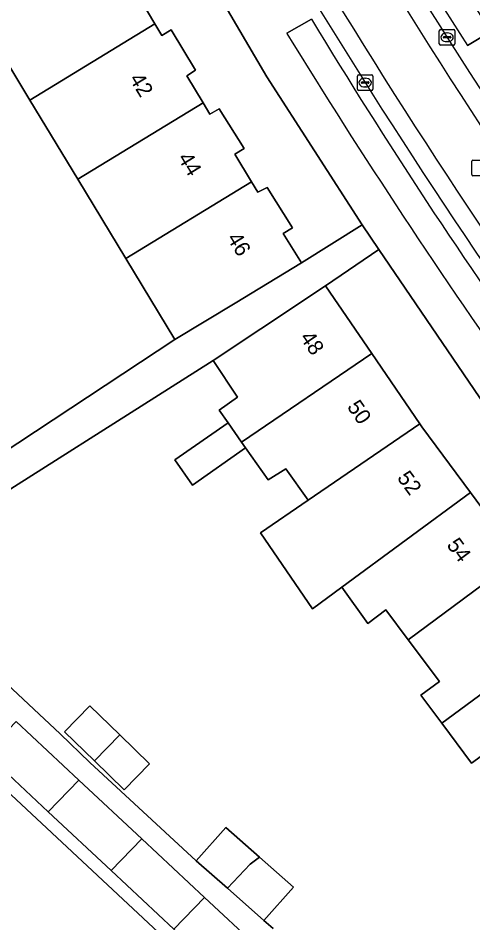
# Model space of a CAD drawing. Extents: x 162073 to 163043, y 381818 to 382561.
# Drawn here: x 162508.8 to 162538.1, y 382247.3 to 382305.6 of the extents above; entities that cross this region are included whole.
import ezdxf

# ---------------------------------------------------------------- set-up
doc = ezdxf.new("R2010")
doc.units = 0
for name, color, linetype in [('IMGEO_Erf', 7, 'Continuous'), ('IMGEO_Fietspad_gesloten', 7, 'Continuous'), ('IMGEO_Kolk', 7, 'Continuous'), ('IMGEO_Pand', 7, 'Continuous'), ('IMGEO_Pand_nummerreeks', 7, 'Continuous'), ('IMGEO_Parkeervlak_open', 7, 'Continuous'), ('IMGEO_Rijbaan_lokaal_open', 7, 'Continuous'), ('IMGEO_Rioolput', 7, 'Continuous'), ('IMGEO_Voetpad_open', 7, 'Continuous')]:
    doc.layers.add(name, color=color, linetype=linetype)

msp = doc.modelspace()

# ---------------------------------------------------------------- linework, layer by layer
at = {"layer": 'IMGEO_Erf'}
for points in [[(162516.63, 382306.92), (162517.645, 382305.206), (162518.089, 382304.457), (162518.686, 382304.825), (162520.246, 382302.222), (162519.701, 382301.866), (162520.745, 382300.11), (162521.172, 382299.391), (162521.781, 382299.733), (162523.38, 382297.169), (162522.784, 382296.8), (162523.864, 382295.026), (162524.268, 382294.363), (162524.877, 382294.667), (162526.501, 382292.052), (162525.892, 382291.696), (162527.085, 382289.792), (162530.981, 382292.245), (162524.856, 382301.801), (162515.515, 382317.726)], [(162518.927, 382284.853), (162515.757, 382290.085), (162512.666, 382295.187), (162509.575, 382300.289), (162506.484, 382305.391)], [(162567.838, 382244.089), (162562.574, 382250), (162557.981, 382255.464), (162545.965, 382270.851), (162540.59, 382278.138), (162532.058, 382290.664), (162528.627, 382288.327), (162531.6, 382283.968), (162534.706, 382279.414), (162534.828, 382279.235), (162537.954, 382275.004), (162541.079, 382270.777), (162544.42, 382266.255), (162547.873, 382261.582), (162547.996, 382261.416), (162551.264, 382257.471), (162554.603, 382253.441), (162557.453, 382250), (162558.225, 382249.068), (162561.821, 382244.727)], [(162457.619, 382263.189), (162459.18, 382261.904), (162475.761, 382248.251), (162478.317, 382251.355), (162474.824, 382254.232), (162476.565, 382256.346), (162480.058, 382253.468), (162483.451, 382257.921), (162481.553, 382259.466), (162483.988, 382262.459), (162486.44, 382265.471), (162488.329, 382263.933), (162488.605, 382263.708), (162491.308, 382267.028), (162489.142, 382268.791), (162491.617, 382271.833), (162493.971, 382274.724), (162496.137, 382272.961), (162498.99, 382276.207), (162500.055, 382275.334), (162502.069, 382273.725), (162502.096, 382273.753), (162518.927, 382284.853)], [(162539.275, 382258.445), (162538.019, 382257.551), (162536.115, 382260.119), (162534.774, 382261.928), (162535.96, 382262.823), (162533.946, 382265.507), (162532.504, 382267.429), (162531.359, 382266.556), (162529.688, 382268.898), (162527.79, 382267.496), (162524.439, 382272.404), (162527.503, 382274.496), (162526.074, 382276.525), (162524.928, 382275.811), (162523.483, 382277.871), (162520.066, 382275.477), (162518.933, 382277.094), (162522.35, 382279.488), (162521.783, 382280.298), (162522.969, 382281.133), (162521.381, 382283.497), (162504.175, 382272.599)], [(162546.943, 382219.45), (162494.331, 382268.629), (162482.206, 382253.929), (162481.569, 382253.156), (162483.282, 382251.74), (162483.952, 382251.186), (162485.979, 382249.511), (162488.441, 382247.475), (162490.227, 382246)], [(162507.097, 382263.591), (162511.538, 382259.449), (162513.452, 382257.589), (162520.303, 382251.26), (162522.204, 382253.41), (162524.377, 382251.488), (162526.565, 382249.554), (162524.664, 382247.404), (162525.253, 382246.883)]]:
    msp.add_lwpolyline(points, dxfattribs=at)
msp.add_lwpolyline([(162515.66, 382255.833), (162513.742, 382257.701), (162511.824, 382259.57), (162513.453, 382261.242), (162515.371, 382259.374), (162517.289, 382257.505)], close=True, dxfattribs=at)
at = {"layer": 'IMGEO_Fietspad_gesloten'}
for centre, radius, start, end in [((162921.44, 382547.896), 456.819, 210.01231, 214.91275), ((162945.03, 382562.574), 483.34, 210.21879, 214.72337), ((162877.852, 382519.575), 408.409, 209.6326, 215.19334), ((162906.267, 382538.255), 443.6, 210.014, 215.04595)]:
    msp.add_arc(centre, radius, start, end, dxfattribs=at)
at = {"layer": 'IMGEO_Kolk'}
for p, q in [((162535.955, 382303.914), (162535.955, 382304.766)), ((162536.03, 382304.84), (162536.882, 382304.84)), ((162536.443, 382304.62), (162536.468, 382304.62)), ((162536.956, 382304.766), (162536.956, 382303.914)), ((162536.214, 382304.334), (162536.214, 382304.346)), ((162536.652, 382304.297), (162536.254, 382304.297)), ((162536.257, 382304.383), (162536.655, 382304.383)), ((162536.466, 382304.06), (162536.441, 382304.06)), ((162536.698, 382304.346), (162536.698, 382304.334)), ((162536.882, 382303.84), (162536.03, 382303.84)), ((162530.68, 382300.992), (162530.68, 382301.844)), ((162530.755, 382301.918), (162531.607, 382301.918)), ((162531.168, 382301.698), (162531.193, 382301.698)), ((162531.681, 382301.844), (162531.681, 382300.992)), ((162530.939, 382301.412), (162530.939, 382301.424)), ((162531.377, 382301.375), (162530.979, 382301.375)), ((162530.982, 382301.461), (162531.38, 382301.461)), ((162531.191, 382301.138), (162531.166, 382301.138)), ((162531.423, 382301.424), (162531.423, 382301.412)), ((162531.607, 382300.918), (162530.755, 382300.918))]:
    msp.add_line(p, q, dxfattribs=at)
for points in [[(162535.955, 382303.914), (162535.955, 382304.766)], [(162536.03, 382304.84), (162536.882, 382304.84)], [(162536.956, 382304.766), (162536.956, 382303.914)], [(162536.882, 382303.84), (162536.03, 382303.84)], [(162530.68, 382300.992), (162530.68, 382301.844)], [(162530.755, 382301.918), (162531.607, 382301.918)], [(162531.681, 382301.844), (162531.681, 382300.992)], [(162531.607, 382300.918), (162530.755, 382300.918)]]:
    msp.add_lwpolyline(points, dxfattribs=at)
for centre, radius, start, end in [((162536.032, 382304.764), 0.0765, 91.55205, 178.44795), ((162536.032, 382304.764), 0.0765, 91.55205, 178.44795), ((162536.88, 382304.764), 0.0765, 1.55205, 88.44795), ((162536.88, 382304.764), 0.0765, 1.55205, 88.44795), ((162536.254, 382304.343), 0.0403, 85.87752, 175.75265), ((162536.251, 382304.333), 0.0366, 178.93798, 274.71019), ((162536.655, 382304.34), 0.043, 264.86636, 352.45326), ((162536.659, 382304.345), 0.0386, 1.73085, 96.63898), ((162536.032, 382303.916), 0.0765, 181.55205, 268.44795), ((162536.032, 382303.916), 0.0765, 181.55205, 268.44795), ((162536.88, 382303.916), 0.0765, 271.55205, 358.44795), ((162536.88, 382303.916), 0.0765, 271.55205, 358.44795), ((162530.757, 382301.842), 0.0765, 91.55205, 178.44795), ((162530.757, 382301.842), 0.0765, 91.55205, 178.44795), ((162531.605, 382301.842), 0.0765, 1.55205, 88.44795), ((162531.605, 382301.842), 0.0765, 1.55205, 88.44795), ((162530.979, 382301.421), 0.0403, 85.87752, 175.75265), ((162530.976, 382301.411), 0.0366, 178.93798, 274.71019), ((162531.38, 382301.418), 0.043, 264.86636, 352.45326), ((162531.384, 382301.423), 0.0386, 1.73085, 96.63898), ((162530.757, 382300.994), 0.0765, 181.55205, 268.44795), ((162530.757, 382300.994), 0.0765, 181.55205, 268.44795), ((162531.605, 382300.994), 0.0765, 271.55205, 358.44795), ((162531.605, 382300.994), 0.0765, 271.55205, 358.44795)]:
    msp.add_arc(centre, radius, start, end, dxfattribs=at)
for centre, major_axis, ratio, start_param, end_param in [((162536.442, 382304.34), (-0.387, 0.002), 0.722429, 4.712389, 7.853982), ((162536.467, 382304.34), (-0.39, 0.002), 0.717154, 1.570796, 4.712389), ((162531.167, 382301.418), (-0.387, 0.002), 0.722429, 4.712389, 7.853982), ((162531.192, 382301.418), (-0.39, 0.002), 0.717154, 1.570796, 4.712389)]:
    msp.add_ellipse(centre, major_axis=major_axis, ratio=ratio, start_param=start_param, end_param=end_param, dxfattribs=at)
at = {"layer": 'IMGEO_Pand'}
for points in [[(162514.538, 382310.298), (162506.484, 382305.391), (162509.575, 382300.289), (162517.645, 382305.206), (162516.63, 382306.92), (162517.176, 382307.25), (162515.577, 382309.891), (162514.968, 382309.535)], [(162512.666, 382295.187), (162520.745, 382300.11), (162519.701, 382301.866), (162520.246, 382302.222), (162518.686, 382304.825), (162518.089, 382304.457), (162517.645, 382305.206), (162509.575, 382300.289)], [(162515.757, 382290.085), (162523.864, 382295.026), (162522.784, 382296.8), (162523.38, 382297.169), (162521.781, 382299.733), (162521.172, 382299.391), (162520.745, 382300.11), (162512.666, 382295.187)], [(162515.757, 382290.085), (162518.927, 382284.853), (162522.808, 382287.203), (162527.085, 382289.792), (162525.892, 382291.696), (162526.501, 382292.052), (162524.877, 382294.667), (162524.268, 382294.363), (162523.864, 382295.026)], [(162531.6, 382283.968), (162528.627, 382288.327), (162524.467, 382285.554), (162521.381, 382283.497), (162522.969, 382281.133), (162521.783, 382280.298), (162522.35, 382279.488), (162523.22, 382278.247)], [(162534.706, 382279.414), (162531.6, 382283.968), (162523.22, 382278.247), (162523.483, 382277.871), (162524.928, 382275.811), (162526.074, 382276.525), (162527.503, 382274.496)], [(162523.22, 382278.247), (162522.35, 382279.488), (162518.933, 382277.094), (162520.066, 382275.477), (162523.483, 382277.871)], [(162537.954, 382275.004), (162534.828, 382279.235), (162534.706, 382279.414), (162527.503, 382274.496), (162524.439, 382272.404), (162527.79, 382267.496), (162529.688, 382268.898)], [(162529.688, 382268.898), (162531.359, 382266.556), (162532.504, 382267.429), (162533.946, 382265.507), (162541.079, 382270.777), (162537.954, 382275.004)], [(162536.115, 382260.119), (162544.42, 382266.255), (162541.079, 382270.777), (162533.946, 382265.507), (162535.96, 382262.823), (162534.774, 382261.928)], [(162547.873, 382261.582), (162544.42, 382266.255), (162536.115, 382260.119), (162538.019, 382257.551), (162539.275, 382258.445), (162540.861, 382256.402)], [(162513.742, 382257.701), (162515.371, 382259.374), (162513.453, 382261.242), (162511.824, 382259.57)], [(162508.699, 382260.23), (162506.728, 382258.193), (162510.772, 382254.409), (162512.745, 382256.45)], [(162515.371, 382259.374), (162513.742, 382257.701), (162515.66, 382255.833), (162517.289, 382257.505)], [(162512.745, 382256.45), (162510.772, 382254.409), (162514.816, 382250.626), (162516.792, 382252.669)], [(162522.313, 382249.483), (162523.766, 382251.039), (162524.377, 382251.488), (162522.204, 382253.41), (162520.303, 382251.26)], [(162518.859, 382246.842), (162520.839, 382248.888), (162516.792, 382252.669), (162514.816, 382250.626)], [(162522.313, 382249.483), (162524.664, 382247.404), (162526.565, 382249.554), (162524.377, 382251.488), (162523.766, 382251.039)], [(162520.839, 382248.888), (162518.859, 382246.842), (162522.903, 382243.059), (162524.885, 382245.108), (162524.196, 382245.752)]]:
    msp.add_lwpolyline(points, close=True, dxfattribs=at)
at = {"layer": 'IMGEO_Parkeervlak_open'}
for points in [[(162527.72, 382305.504), (162526.137, 382304.596)], [(162537.771, 382303.803), (162539.283, 382304.709)]]:
    msp.add_lwpolyline(points, dxfattribs=at)
for centre, radius, start, end in [((162814.64, 382483.49), 328.305, 207.88317, 212.99454), ((162875.039, 382520.377), 400.816, 208.50438, 212.70626), ((162845.651, 382497.975), 371.652, 211.1902, 215.47235), ((162885.978, 382525.172), 422.066, 211.50759, 215.30158)]:
    msp.add_arc(centre, radius, start, end, dxfattribs=at)
at = {"layer": 'IMGEO_Rijbaan_lokaal_open'}
for centre, radius, start, end in [((162921.44, 382547.896), 456.819, 210.01231, 214.91275), ((162877.852, 382519.575), 408.409, 209.6326, 215.19334)]:
    msp.add_arc(centre, radius, start, end, dxfattribs=at)
at = {"layer": 'IMGEO_Rioolput'}
for p, q in [((162538.117, 382296.42), (162538.969, 382296.42)), ((162538.042, 382295.494), (162538.042, 382296.346)), ((162538.969, 382295.42), (162538.117, 382295.42))]:
    msp.add_line(p, q, dxfattribs=at)
for points in [[(162538.117, 382296.42), (162538.969, 382296.42)], [(162538.042, 382295.494), (162538.042, 382296.346)], [(162538.969, 382295.42), (162538.117, 382295.42)]]:
    msp.add_lwpolyline(points, dxfattribs=at)
for centre, start, end in [((162538.119, 382296.344), 91.55205, 178.44795), ((162538.119, 382296.344), 91.55205, 178.44795), ((162538.119, 382295.496), 181.55205, 268.44795), ((162538.119, 382295.496), 181.55205, 268.44795)]:
    msp.add_arc(centre, 0.0765, start, end, dxfattribs=at)
at = {"layer": 'IMGEO_Voetpad_open'}
for points in [[(162515.515, 382317.726), (162524.856, 382301.801), (162530.981, 382292.245), (162532.058, 382290.664), (162540.59, 382278.138), (162545.965, 382270.851), (162557.981, 382255.464), (162562.574, 382250), (162567.838, 382244.089), (162572.157, 382239.239), (162572.556, 382238.82), (162573.298, 382238.041), (162584.822, 382225.942), (162592.043, 382218.91), (162605.774, 382206.205), (162621.309, 382192.475), (162624.656, 382189.517), (162626.716, 382187.697), (162638.741, 382177.42), (162641.717, 382174.636)], [(162526.137, 382304.596), (162527.72, 382305.504)], [(162539.081, 382301.736), (162540.405, 382302.413), (162539.283, 382304.709), (162537.771, 382303.803)], [(162504.175, 382272.599), (162521.381, 382283.497), (162524.467, 382285.554), (162528.627, 382288.327), (162532.058, 382290.664), (162530.981, 382292.245), (162527.085, 382289.792), (162522.808, 382287.203), (162518.927, 382284.853), (162502.096, 382273.753)], [(162494.331, 382268.629), (162546.943, 382219.45)], [(162525.253, 382246.883), (162524.664, 382247.404), (162522.313, 382249.483), (162520.303, 382251.26), (162513.452, 382257.589), (162511.538, 382259.449), (162507.097, 382263.591)], [(162508.699, 382260.23), (162512.745, 382256.45), (162516.792, 382252.669), (162520.839, 382248.888), (162524.196, 382245.752)], [(162518.859, 382246.842), (162514.816, 382250.626), (162510.772, 382254.409), (162506.728, 382258.193)]]:
    msp.add_lwpolyline(points, dxfattribs=at)
for centre, radius, start, end in [((162814.64, 382483.49), 328.305, 207.88317, 212.99454), ((162875.039, 382520.377), 400.816, 208.50438, 212.70626), ((162945.03, 382562.574), 483.34, 210.21879, 214.72337), ((162906.267, 382538.255), 443.6, 210.014, 215.04595), ((162845.651, 382497.975), 371.652, 211.1902, 215.47235), ((162885.978, 382525.172), 422.066, 211.50759, 215.30158)]:
    msp.add_arc(centre, radius, start, end, dxfattribs=at)

# ---------------------------------------------------------------- texts
at = {"layer": 'IMGEO_Pand_nummerreeks'}
for s, rotation, p in [('42', 301.31026, (162515.961, 382301.662)), ('44', 301.53376, (162519.077, 382296.557)), ('46', 301.60597, (162522.248, 382291.393)), ('48', 304.29704, (162526.94, 382284.98)), ('50', 304.29704, (162529.979, 382280.523)), ('52', 306.37688, (162533.197, 382275.931)), ('54', 306.4639, (162536.387, 382271.606))]:
    msp.add_text(s, height=1, rotation=rotation, dxfattribs=at).set_placement(p)

doc.saveas('drawing.dxf')
